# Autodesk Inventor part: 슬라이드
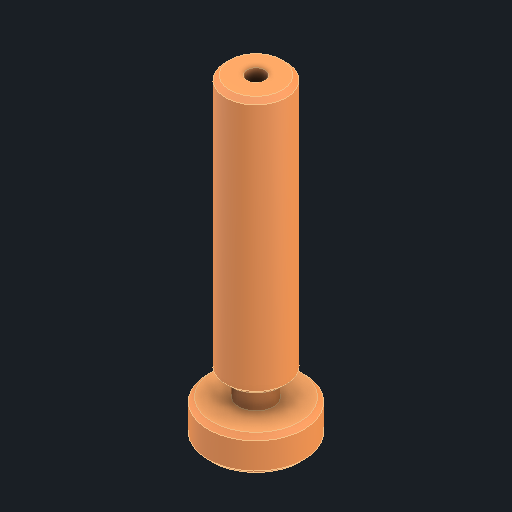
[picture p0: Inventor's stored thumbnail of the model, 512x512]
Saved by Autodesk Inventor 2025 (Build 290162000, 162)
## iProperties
Created: 2025-08
Part Number: 슬라이드
Material: 강철, 연강
Document SubType Name: Modeling
Designer: infra10
Density: 7.86 g/cm^3
Appearance: 기본값
Author: jhkim
Sending System: Autodesk Inventor 2026
Preprocessor: ST-DEVELOPER v20.1
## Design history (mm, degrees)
feature "솔리드1"
node "솔리드2"
